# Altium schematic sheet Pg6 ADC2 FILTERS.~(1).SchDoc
size 431 x 279 mm; Date: Not shown in title block; ApprovedBy: Not shown in title block; CheckedBy: Not shown in title block; Author: Not shown in title block; CompanyName: Not shown in title block; Engineer: Not shown in title block; Organization: Not shown in title block; Address1: Not shown in title block; Address2: Not shown in title block; Address3: Not shown in title block; Address4: Not shown in title block; DocumentNumber: 7; Revision: Use project parameter SCH_Rev; SheetNumber: 6; SheetTotal: 8; PageSetup: Record=PageOptions|CenterHorizontal=True|CenterVertical=True|PrintScale=0.64|XCorrection=1.00|YCorrection=1.00|PrintKind=0|BorderSize=5000000|LeftOffset=0|BottomOffset=0|Orientation=2|PaperLength=1000|PaperWidth=1000|Scale=100|PaperSource=15|PrintQuality=600|MediaType=1|DitherType=10|PaperKind=Letter|PrintScaleMode=1
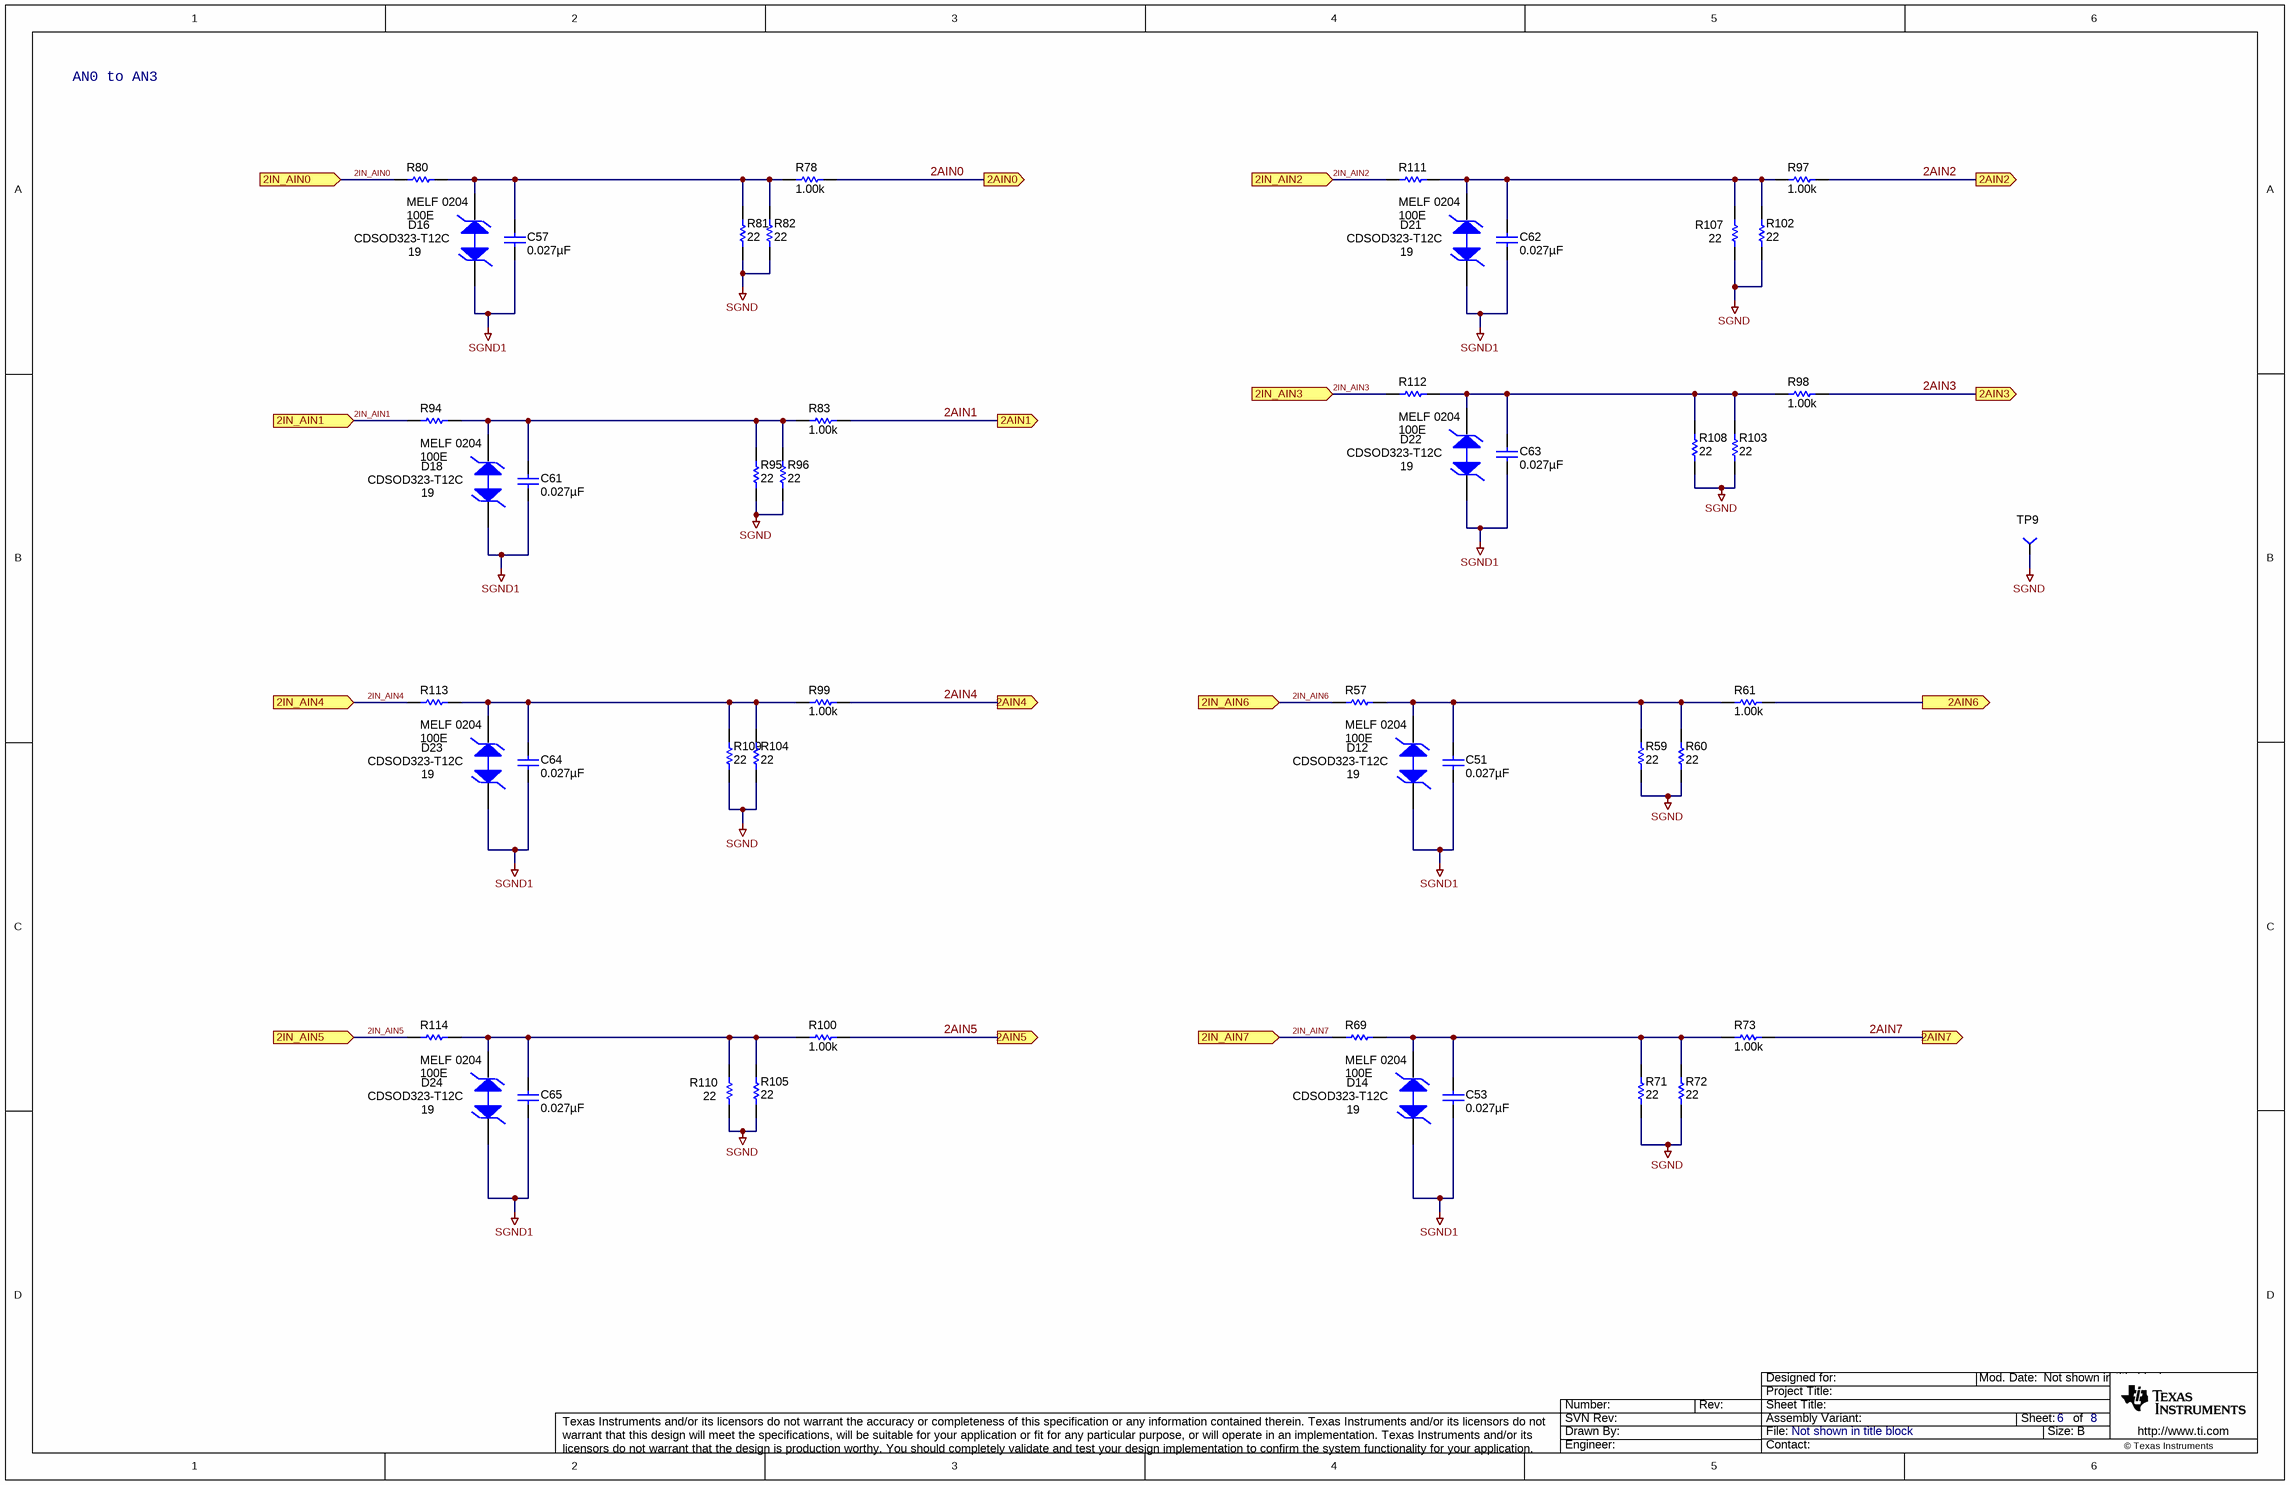
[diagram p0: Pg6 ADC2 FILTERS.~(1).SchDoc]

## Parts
C51  ValueDisplayed: 0.027µF  [1206]  (hidden comment: GRM3195C1H273JA01D)
C53  ValueDisplayed: 0.027µF  [1206]  (hidden comment: GRM3195C1H273JA01D)
C57  ValueDisplayed: 0.027µF  [1206]  (hidden comment: GRM3195C1H273JA01D)
C61  ValueDisplayed: 0.027µF  [1206]  (hidden comment: GRM3195C1H273JA01D)
C62  ValueDisplayed: 0.027µF  [1206]  (hidden comment: GRM3195C1H273JA01D)
C63  ValueDisplayed: 0.027µF  [1206]  (hidden comment: GRM3195C1H273JA01D)
C64  ValueDisplayed: 0.027µF  [1206]  (hidden comment: GRM3195C1H273JA01D)
C65  ValueDisplayed: 0.027µF  [1206]  (hidden comment: GRM3195C1H273JA01D)
D12  CDSOD323-T12C  value 19  [sod-323]
D14  CDSOD323-T12C  value 19  [sod-323]
D16  CDSOD323-T12C  value 19  [sod-323]
D18  CDSOD323-T12C  value 19  [sod-323]
D21  CDSOD323-T12C  value 19  [sod-323]
D22  CDSOD323-T12C  value 19  [sod-323]
D23  CDSOD323-T12C  value 19  [sod-323]
D24  CDSOD323-T12C  value 19  [sod-323]
R57  value 100E  PackageReference: MELF 0204  [1206]  (hidden comment: MMA02040C1000FB300)
R59  value 22  [0603]  (hidden comment: CRCW060322R0FKEA)
R60  value 22  [0603]  (hidden comment: CRCW060322R0FKEA)
R61  value 1.00k  [0603]  (hidden comment: CRCW06031K00FKEA)
R69  value 100E  PackageReference: MELF 0204  [1206]  (hidden comment: MMA02040C1000FB300)
R71  value 22  [0603]  (hidden comment: CRCW060322R0FKEA)
R72  value 22  [0603]  (hidden comment: CRCW060322R0FKEA)
R73  value 1.00k  [0603]  (hidden comment: CRCW06031K00FKEA)
R78  value 1.00k  [0603]  (hidden comment: CRCW06031K00FKEA)
R80  value 100E  PackageReference: MELF 0204  [1206]  (hidden comment: MMA02040C1000FB300)
R81  value 22  [0603]  (hidden comment: CRCW060322R0FKEA)
R82  value 22  [0603]  (hidden comment: CRCW060322R0FKEA)
R83  value 1.00k  [0603]  (hidden comment: CRCW06031K00FKEA)
R94  value 100E  PackageReference: MELF 0204  [1206]  (hidden comment: MMA02040C1000FB300)
R95  value 22  [0603]  (hidden comment: CRCW060322R0FKEA)
R96  value 22  [0603]  (hidden comment: CRCW060322R0FKEA)
R97  value 1.00k  [0603]  (hidden comment: CRCW06031K00FKEA)
R98  value 1.00k  [0603]  (hidden comment: CRCW06031K00FKEA)
R99  value 1.00k  [0603]  (hidden comment: CRCW06031K00FKEA)
R100  value 1.00k  [0603]  (hidden comment: CRCW06031K00FKEA)
R102  value 22  [0603]  (hidden comment: CRCW060322R0FKEA)
R103  value 22  [0603]  (hidden comment: CRCW060322R0FKEA)
R104  value 22  [0603]  (hidden comment: CRCW060322R0FKEA)
R105  value 22  [0603]  (hidden comment: CRCW060322R0FKEA)
R107  value 22  [0603]  (hidden comment: CRCW060322R0FKEA)
R108  value 22  [0603]  (hidden comment: CRCW060322R0FKEA)
R109  value 22  [0603]  (hidden comment: CRCW060322R0FKEA)
R110  value 22  [0603]  (hidden comment: CRCW060322R0FKEA)
R111  value 100E  PackageReference: MELF 0204  [1206]  (hidden comment: MMA02040C1000FB300)
R112  value 100E  PackageReference: MELF 0204  [1206]  (hidden comment: MMA02040C1000FB300)
R113  value 100E  PackageReference: MELF 0204  [1206]  (hidden comment: MMA02040C1000FB300)
R114  value 100E  PackageReference: MELF 0204  [1206]  (hidden comment: MMA02040C1000FB300)
TP9  TP1_PD40_D0.5_S50  [TP1_PD40_D0.5_S50]  (value not drawn)

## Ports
2AIN0 (out), 2AIN1 (out), 2AIN2 (out), 2AIN3 (out), 2AIN4 (out), 2AIN5 (out), 2AIN6 (out), 2AIN7 (out), 2IN_AIN0 (in), 2IN_AIN1 (in), 2IN_AIN2 (in), 2IN_AIN3 (in), 2IN_AIN4 (in), 2IN_AIN5 (in), 2IN_AIN6 (in), 2IN_AIN7 (in)

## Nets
SGND: R59.1 R60.1 R71.1 R72.1 R81.1 R82.1 R95.1 R96.1 R102.1 R103.1 R104.1 R105.1 R107.1 R108.1 R109.1 R110.1 TP9.1
SGND1: C51.2 C53.2 C57.2 C61.2 C62.2 C63.2 C64.2 C65.2 D12.2 D14.2 D16.2 D18.2 D21.2 D22.2 D23.2 D24.2
2AIN0: R78.2 ; port 2AIN0
2AIN1: R83.2 ; port 2AIN1
2AIN2: R97.2 ; port 2AIN2
2AIN3: R98.2 ; port 2AIN3
2AIN4: R99.2 ; port 2AIN4
2AIN5: R100.2 ; port 2AIN5
2AIN6: R61.2 ; port 2AIN6
2AIN7: R73.2 ; port 2AIN7
2IN_AIN0: R80.1 ; port 2IN_AIN0
2IN_AIN1: R94.1 ; port 2IN_AIN1
2IN_AIN2: R111.1 ; port 2IN_AIN2
2IN_AIN3: R112.1 ; port 2IN_AIN3
2IN_AIN4: R113.1 ; port 2IN_AIN4
2IN_AIN5: R114.1 ; port 2IN_AIN5
2IN_AIN6: R57.1 ; port 2IN_AIN6
2IN_AIN7: R69.1 ; port 2IN_AIN7
NetC51_1: C51.1 D12.1 R57.2 R59.2 R60.2 R61.1
NetC53_1: C53.1 D14.1 R69.2 R71.2 R72.2 R73.1
NetC57_1: C57.1 D16.1 R78.1 R80.2 R81.2 R82.2
NetC61_1: C61.1 D18.1 R83.1 R94.2 R95.2 R96.2
NetC62_1: C62.1 D21.1 R97.1 R102.2 R107.2 R111.2
NetC63_1: C63.1 D22.1 R98.1 R103.2 R108.2 R112.2
NetC64_1: C64.1 D23.1 R99.1 R104.2 R109.2 R113.2
NetC65_1: C65.1 D24.1 R100.1 R105.2 R110.2 R114.2

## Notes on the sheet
- AN0 to AN3

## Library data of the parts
C51 C53 C57 C61-C65 = GRM3195C1H273JA01D: CAP, CERM, 0.027uF, 50V, +/-5%, C0G/NP0, 1206; Manufacturer: MuRata; Polarized: N; CompType: Capacitor; U/M: EA; Cap_F: 0.000000027; Tolerance_%: 5; Value1: Unknown; VDC_V: 50; TaMin_C: -55; TaMax_C: 125
D12 D14 D16 D18 D21-D24 = CDSOD323-T15SC: Diode, TVS, ARRAY, 19V, SOD323; Manufacturer: Bourns Inc.
R57 R69 R80 R94 R111-R114 = MMA02040C1000FB300: RES 100 OHM .4W 1% 0204 MELF; Manufacturer: Vishay Beyschlag; CompType: Resistor; Power_W: 0.5
R59 R60 R71 R72 R81 R82 R95 R96 R102-R105 R107-R110 = CRCW060322R0JNEA: RES, 22 ohm, 1%, 0.1W, 0603; Manufacturer: Vishay-Dale; CompType: Resistor; Value_Code: 22R0; Tolerance_%: 1; Power_W: 0.1; VDC_V: 75; TempCo: 200 ppm/C; EIA_Code: E24; U/M: EA
R61 R73 R78 R83 R97-R100 = CRCW06031K00FKEA: RES, 1.00k ohm, 1%, 0.1W, 0603; Manufacturer: Vishay-Dale; CompType: Resistor; Res_ohm: 1000; Value_Code: 1k00; Tolerance_%: 1; Power_W: 0.1; VDC_V: 75; TempCo: 100 ppm/C; EIA_Code: E96; U/M: EA
TP9 = TP-040_RND: Test Point 40mil pad 20mil drill; Manufacturer: STD; Description: Test Point, O.040 Hole; Value: STD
